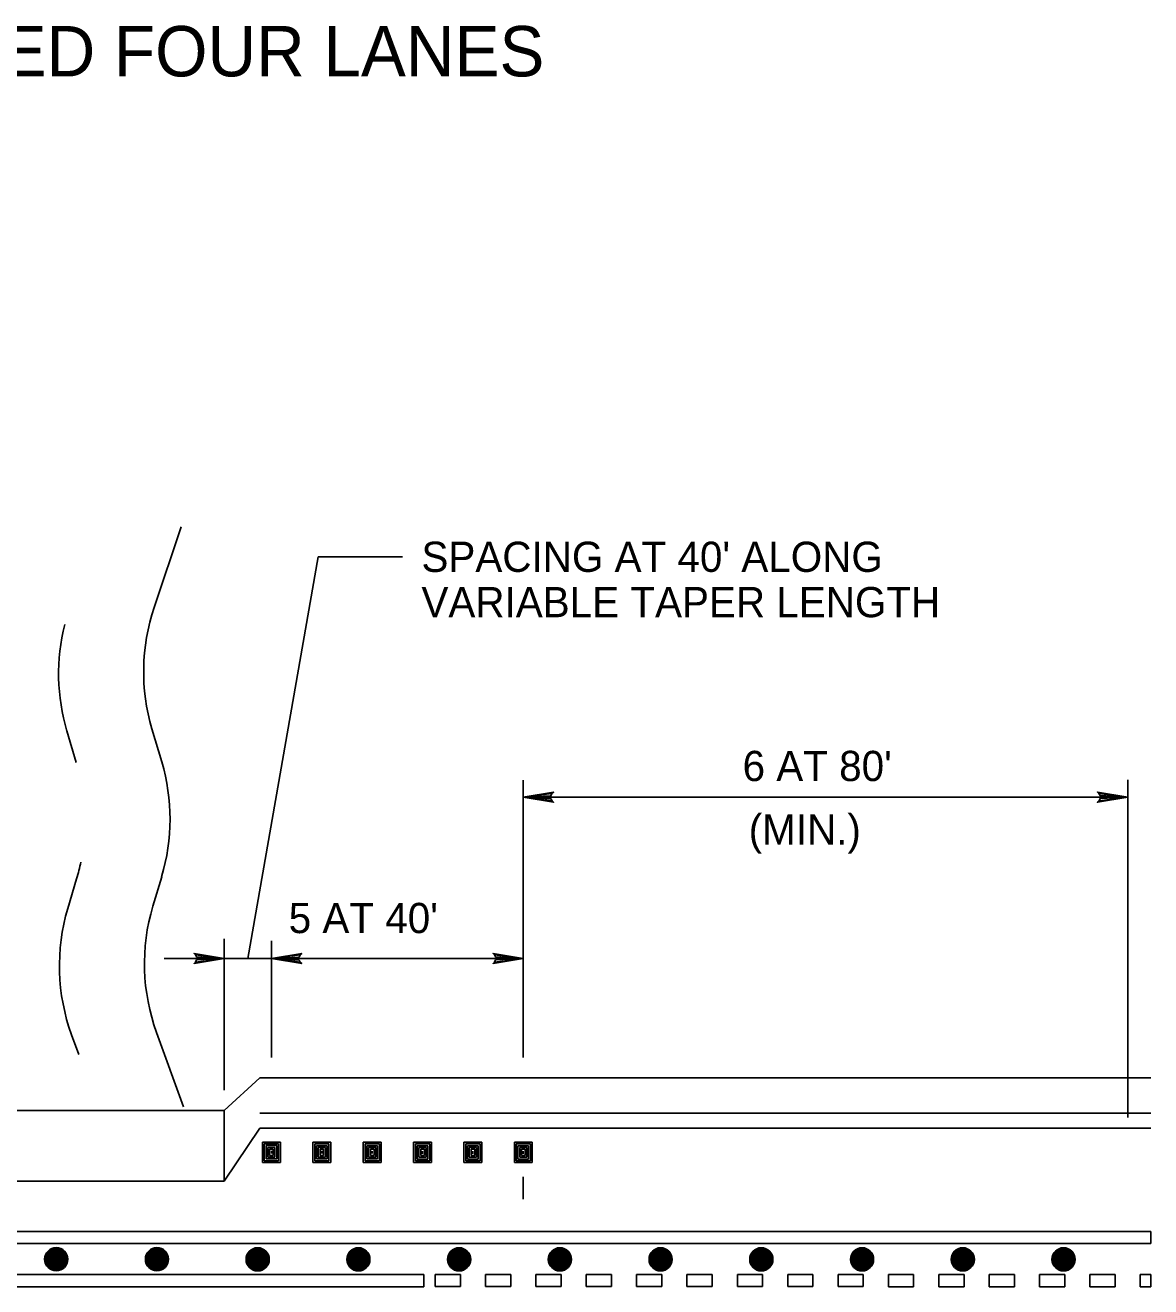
# Model space of a CAD drawing. Extents: x 639362 to 641108, y 298458 to 299646.
# Drawn here: x 640689.2 to 640800.9, y 299355.1 to 299480.3 of the extents above; entities that cross this region are included whole.
import ezdxf

# ---------------------------------------------------------------- set-up
doc = ezdxf.new("R2010")
doc.units = 0
doc.layers.add('2', color=7, linetype='Continuous')
doc.layers.add('3', color=7, linetype='Continuous')

# ---------------------------------------------------------------- blocks, each defined once
blk = doc.blocks.new('RARROW')
at = {"layer": '3'}
blk.add_lwpolyline([(-2.2695, 0.285), (-2.184875, 0.12075), (0, 0), (-2.2695, 0.285), (-2.38575, 0.384625), (0, 0), (-2.183125, -0.108), (-2.262875, -0.2705), (0, 0), (-2.38575, -0.379125), (-2.262875, -0.2705)], dxfattribs=at)

msp = doc.modelspace()

# ---------------------------------------------------------------- linework, layer by layer
at = {"layer": '2'}
for p, q in [((640704.67, 299430.52), (640701.99, 299422.54)), ((640718.27, 299427.55), (640711.31, 299387.69)), ((640718.27, 299427.55), (640726.64, 299427.55)), ((640693.33, 299410.27), (640694.26, 299407.14)), ((640701.77, 299410.48), (640702.75, 299407.2)), ((640738.64, 299405.38), (640738.64, 299377.85)), ((640798.64, 299405.43), (640798.64, 299371.92)), ((640738.64, 299403.7), (640798.64, 299403.7)), ((640702.74, 299395.81), (640701.86, 299392.88)), ((640694.3, 299395.6), (640693.42, 299392.66)), ((640708.95, 299389.65), (640708.95, 299374.61)), ((640713.64, 299389.43), (640713.64, 299377.85)), ((640703, 299387.69), (640713.64, 299387.69)), ((640713.64, 299387.69), (640738.64, 299387.69)), ((640693.79, 299380.12), (640694.51, 299378.15)), ((640702.24, 299380.33), (640704.91, 299372.97)), ((640712.47, 299375.85), (640708.95, 299372.61)), ((640712.47, 299375.85), (640800.93, 299375.85)), ((640671.45, 299372.61), (640708.95, 299372.61)), ((640708.95, 299372.61), (640708.95, 299365.58)), ((640712.47, 299372.35), (640800.93, 299372.35)), ((640712.47, 299370.85), (640708.95, 299365.58)), ((640712.47, 299370.85), (640800.93, 299370.85)), ((640712.75, 299369.47), (640714.53, 299369.47)), ((640712.75, 299367.43), (640712.75, 299369.47)), ((640714.53, 299369.47), (640714.53, 299367.43)), ((640717.75, 299369.47), (640719.53, 299369.47)), ((640717.75, 299367.43), (640717.75, 299369.47)), ((640719.53, 299369.47), (640719.53, 299367.43)), ((640722.75, 299369.47), (640724.53, 299369.47)), ((640722.75, 299367.43), (640722.75, 299369.47)), ((640724.53, 299369.47), (640724.53, 299367.43)), ((640727.75, 299369.47), (640729.53, 299369.47)), ((640727.75, 299367.43), (640727.75, 299369.47)), ((640729.53, 299369.47), (640729.53, 299367.43)), ((640732.75, 299369.47), (640734.53, 299369.47)), ((640732.75, 299367.43), (640732.75, 299369.47)), ((640734.53, 299369.47), (640734.53, 299367.43)), ((640737.75, 299369.47), (640739.53, 299369.47)), ((640737.75, 299367.43), (640737.75, 299369.47)), ((640739.53, 299369.47), (640739.53, 299367.43)), ((640712.93, 299369.29), (640714.35, 299369.29)), ((640712.93, 299367.61), (640712.93, 299369.29)), ((640713.11, 299369.12), (640714.17, 299369.12)), ((640713.11, 299367.79), (640713.11, 299369.12)), ((640713.28, 299367.96), (640713.28, 299368.94)), ((640713.28, 299368.94), (640713.99, 299368.94)), ((640713.46, 299368.76), (640713.82, 299368.76)), ((640713.46, 299368.14), (640713.46, 299368.76)), ((640713.82, 299368.14), (640713.46, 299368.14)), ((640713.64, 299368.59), (640713.64, 299368.32)), ((640713.82, 299368.76), (640713.82, 299368.14)), ((640713.99, 299368.94), (640713.99, 299367.96)), ((640714.17, 299369.12), (640714.17, 299367.79)), ((640714.35, 299369.29), (640714.35, 299367.61)), ((640717.93, 299369.29), (640719.35, 299369.29)), ((640717.93, 299367.61), (640717.93, 299369.29)), ((640718.11, 299369.11), (640719.17, 299369.11)), ((640718.11, 299367.79), (640718.11, 299369.11)), ((640718.28, 299367.96), (640718.28, 299368.94)), ((640718.28, 299368.94), (640718.99, 299368.94)), ((640718.46, 299368.76), (640718.82, 299368.76)), ((640718.46, 299368.14), (640718.46, 299368.76)), ((640718.82, 299368.14), (640718.46, 299368.14)), ((640718.64, 299368.59), (640718.64, 299368.32)), ((640718.82, 299368.76), (640718.82, 299368.14)), ((640718.99, 299368.94), (640718.99, 299367.96)), ((640719.17, 299369.11), (640719.17, 299367.79)), ((640719.35, 299369.29), (640719.35, 299367.61)), ((640722.93, 299369.29), (640724.35, 299369.29)), ((640722.93, 299367.61), (640722.93, 299369.29)), ((640723.11, 299369.11), (640724.17, 299369.11)), ((640723.11, 299367.79), (640723.11, 299369.11)), ((640723.28, 299367.96), (640723.28, 299368.94)), ((640723.28, 299368.94), (640723.99, 299368.94)), ((640723.46, 299368.76), (640723.82, 299368.76)), ((640723.46, 299368.14), (640723.46, 299368.76)), ((640723.82, 299368.14), (640723.46, 299368.14)), ((640723.64, 299368.58), (640723.64, 299368.32)), ((640723.82, 299368.76), (640723.82, 299368.14)), ((640723.99, 299368.94), (640723.99, 299367.96)), ((640724.17, 299369.11), (640724.17, 299367.79)), ((640724.35, 299369.29), (640724.35, 299367.61)), ((640727.93, 299369.29), (640729.35, 299369.29)), ((640727.93, 299367.61), (640727.93, 299369.29)), ((640728.11, 299369.11), (640729.17, 299369.11)), ((640728.11, 299367.78), (640728.11, 299369.11)), ((640728.28, 299367.96), (640728.28, 299368.94)), ((640728.28, 299368.94), (640728.99, 299368.94)), ((640728.46, 299368.76), (640728.82, 299368.76)), ((640728.46, 299368.14), (640728.46, 299368.76)), ((640728.64, 299368.58), (640728.64, 299368.31)), ((640728.82, 299368.76), (640728.82, 299368.14)), ((640728.99, 299368.94), (640728.99, 299367.96)), ((640729.17, 299369.11), (640729.17, 299367.78)), ((640729.35, 299369.29), (640729.35, 299367.61)), ((640732.93, 299369.29), (640734.35, 299369.29)), ((640732.93, 299367.6), (640732.93, 299369.29)), ((640733.11, 299369.11), (640734.17, 299369.11)), ((640733.11, 299367.78), (640733.11, 299369.11)), ((640733.28, 299367.96), (640733.28, 299368.93)), ((640733.28, 299368.93), (640733.99, 299368.93)), ((640733.46, 299368.76), (640733.82, 299368.76)), ((640733.46, 299368.14), (640733.46, 299368.76)), ((640733.64, 299368.58), (640733.64, 299368.31)), ((640733.82, 299368.76), (640733.82, 299368.14)), ((640733.99, 299368.93), (640733.99, 299367.96)), ((640734.17, 299369.11), (640734.17, 299367.78)), ((640734.35, 299369.29), (640734.35, 299367.6)), ((640737.93, 299369.29), (640739.35, 299369.29)), ((640737.93, 299367.6), (640737.93, 299369.29)), ((640738.11, 299369.11), (640739.17, 299369.11)), ((640738.11, 299367.78), (640738.11, 299369.11)), ((640738.28, 299367.96), (640738.28, 299368.93)), ((640738.28, 299368.93), (640738.99, 299368.93)), ((640738.46, 299368.76), (640738.82, 299368.76)), ((640738.46, 299368.14), (640738.46, 299368.76)), ((640738.64, 299368.58), (640738.64, 299368.31)), ((640738.82, 299368.76), (640738.82, 299368.14)), ((640738.99, 299368.93), (640738.99, 299367.96)), ((640739.17, 299369.11), (640739.17, 299367.78)), ((640739.35, 299369.29), (640739.35, 299367.6)), ((640714.53, 299367.43), (640712.75, 299367.43)), ((640714.35, 299367.61), (640712.93, 299367.61)), ((640714.17, 299367.79), (640713.11, 299367.79)), ((640713.99, 299367.96), (640713.28, 299367.96)), ((640719.53, 299367.43), (640717.75, 299367.43)), ((640719.35, 299367.61), (640717.93, 299367.61)), ((640719.17, 299367.79), (640718.11, 299367.79)), ((640718.99, 299367.96), (640718.28, 299367.96)), ((640724.53, 299367.43), (640722.75, 299367.43)), ((640724.35, 299367.61), (640722.93, 299367.61)), ((640724.17, 299367.79), (640723.11, 299367.79)), ((640723.99, 299367.96), (640723.28, 299367.96)), ((640729.53, 299367.43), (640727.75, 299367.43)), ((640729.35, 299367.61), (640727.93, 299367.61)), ((640729.17, 299367.78), (640728.11, 299367.78)), ((640728.99, 299367.96), (640728.28, 299367.96)), ((640728.82, 299368.14), (640728.46, 299368.14)), ((640734.53, 299367.43), (640732.75, 299367.43)), ((640734.35, 299367.6), (640732.93, 299367.6)), ((640734.17, 299367.78), (640733.11, 299367.78)), ((640733.99, 299367.96), (640733.28, 299367.96)), ((640733.82, 299368.14), (640733.46, 299368.14)), ((640739.53, 299367.43), (640737.75, 299367.43)), ((640739.35, 299367.6), (640737.93, 299367.6)), ((640739.17, 299367.78), (640738.11, 299367.78)), ((640738.99, 299367.96), (640738.28, 299367.96)), ((640738.82, 299368.14), (640738.46, 299368.14)), ((640738.64, 299366.01), (640738.64, 299363.8)), ((640671.45, 299365.58), (640708.95, 299365.58)), ((640652.18, 299360.61), (640800.93, 299360.61)), ((640800.93, 299359.41), (640652.18, 299359.41)), ((640800.93, 299360.61), (640800.93, 299359.41)), ((640577.73, 299356.31), (640728.77, 299356.31)), ((640728.77, 299356.31), (640728.77, 299355.11)), ((640729.89, 299356.33), (640729.89, 299355.13)), ((640732.39, 299356.33), (640729.89, 299356.33)), ((640732.39, 299355.13), (640732.39, 299356.33)), ((640734.89, 299356.33), (640734.89, 299355.13)), ((640737.39, 299356.33), (640734.89, 299356.33)), ((640737.39, 299355.13), (640737.39, 299356.33)), ((640739.89, 299356.32), (640739.89, 299355.12)), ((640742.39, 299356.32), (640739.89, 299356.32)), ((640742.39, 299355.12), (640742.39, 299356.32)), ((640744.89, 299356.32), (640744.89, 299355.12)), ((640747.39, 299356.32), (640744.89, 299356.32)), ((640747.39, 299355.12), (640747.39, 299356.32)), ((640749.89, 299356.32), (640749.89, 299355.12)), ((640752.39, 299356.32), (640749.89, 299356.32)), ((640752.39, 299355.12), (640752.39, 299356.32)), ((640754.89, 299356.32), (640754.89, 299355.12)), ((640757.39, 299356.32), (640754.89, 299356.32)), ((640757.39, 299355.12), (640757.39, 299356.32)), ((640759.89, 299356.32), (640759.89, 299355.12)), ((640762.39, 299356.32), (640759.89, 299356.32)), ((640762.39, 299355.12), (640762.39, 299356.32)), ((640764.89, 299356.32), (640764.89, 299355.12)), ((640767.39, 299356.32), (640764.89, 299356.32)), ((640767.39, 299355.12), (640767.39, 299356.32)), ((640769.89, 299356.32), (640769.89, 299355.12)), ((640772.39, 299356.32), (640769.89, 299356.32)), ((640772.39, 299355.12), (640772.39, 299356.32)), ((640774.89, 299356.32), (640774.89, 299355.11)), ((640777.39, 299356.32), (640774.89, 299356.32)), ((640777.39, 299355.11), (640777.39, 299356.32)), ((640779.89, 299356.31), (640779.89, 299355.11)), ((640782.39, 299356.31), (640779.89, 299356.31)), ((640782.39, 299355.11), (640782.39, 299356.31)), ((640784.89, 299356.31), (640784.89, 299355.11)), ((640787.39, 299356.31), (640784.89, 299356.31)), ((640787.39, 299355.11), (640787.39, 299356.31)), ((640789.89, 299356.31), (640789.89, 299355.11)), ((640792.39, 299356.31), (640789.89, 299356.31)), ((640792.39, 299355.11), (640792.39, 299356.31)), ((640794.89, 299356.31), (640794.89, 299355.11)), ((640797.39, 299356.31), (640794.89, 299356.31)), ((640797.39, 299355.11), (640797.39, 299356.31)), ((640799.89, 299355.11), (640799.89, 299356.31)), ((640799.89, 299356.31), (640800.93, 299356.31)), ((640800.93, 299356.31), (640800.93, 299355.11)), ((640728.77, 299355.11), (640577.73, 299355.11)), ((640729.89, 299355.13), (640732.39, 299355.13)), ((640734.89, 299355.12), (640737.39, 299355.12)), ((640739.89, 299355.12), (640742.39, 299355.12)), ((640744.89, 299355.12), (640747.39, 299355.12)), ((640749.89, 299355.12), (640752.39, 299355.12)), ((640754.89, 299355.12), (640757.39, 299355.12)), ((640759.89, 299355.12), (640762.39, 299355.12)), ((640764.89, 299355.12), (640767.39, 299355.12)), ((640769.89, 299355.12), (640772.39, 299355.12)), ((640774.89, 299355.11), (640777.39, 299355.11)), ((640779.89, 299355.11), (640782.39, 299355.11)), ((640784.89, 299355.11), (640787.39, 299355.11)), ((640789.89, 299355.11), (640792.39, 299355.11)), ((640794.89, 299355.11), (640797.39, 299355.11)), ((640800.93, 299355.11), (640799.89, 299355.11)), ((640799.89, 299355.11), (640799.89, 299355.11))]:
    msp.add_line(p, q, dxfattribs=at)
for centre, radius in [((640692.27, 299357.84), 1.15), ((640692.27, 299357.84), 1.07), ((640692.27, 299357.84), 0.985), ((640692.27, 299357.84), 0.904), ((640692.27, 299357.84), 0.822), ((640692.27, 299357.84), 0.741), ((640692.27, 299357.84), 0.659), ((640692.27, 299357.84), 0.578), ((640692.27, 299357.84), 0.496), ((640692.27, 299357.84), 0.414), ((640692.27, 299357.84), 0.333), ((640702.27, 299357.84), 1.15), ((640702.27, 299357.84), 1.07), ((640702.27, 299357.84), 0.985), ((640702.27, 299357.84), 0.904), ((640702.27, 299357.84), 0.822), ((640702.27, 299357.84), 0.741), ((640702.27, 299357.84), 0.659), ((640702.27, 299357.84), 0.578), ((640702.27, 299357.84), 0.496), ((640702.27, 299357.84), 0.414), ((640702.27, 299357.84), 0.333), ((640712.27, 299357.83), 1.15), ((640712.27, 299357.83), 1.07), ((640712.27, 299357.83), 0.985), ((640712.27, 299357.83), 0.904), ((640712.27, 299357.83), 0.822), ((640712.27, 299357.83), 0.741), ((640712.27, 299357.83), 0.659), ((640712.27, 299357.83), 0.578), ((640712.27, 299357.83), 0.496), ((640712.27, 299357.83), 0.414), ((640712.27, 299357.83), 0.333), ((640722.27, 299357.83), 1.15), ((640722.27, 299357.83), 1.07), ((640722.27, 299357.83), 0.985), ((640722.27, 299357.83), 0.904), ((640722.27, 299357.83), 0.822), ((640722.27, 299357.83), 0.741), ((640722.27, 299357.83), 0.659), ((640722.27, 299357.83), 0.578), ((640722.27, 299357.83), 0.496), ((640722.27, 299357.83), 0.414), ((640722.27, 299357.83), 0.333), ((640732.27, 299357.83), 1.15), ((640732.27, 299357.83), 1.07), ((640732.27, 299357.83), 0.985), ((640732.27, 299357.83), 0.904), ((640732.27, 299357.83), 0.822), ((640732.27, 299357.83), 0.741), ((640732.27, 299357.83), 0.659), ((640732.27, 299357.83), 0.578), ((640732.27, 299357.83), 0.496), ((640732.27, 299357.83), 0.414), ((640732.27, 299357.83), 0.333), ((640742.27, 299357.83), 1.15), ((640742.27, 299357.83), 1.07), ((640742.27, 299357.83), 0.985), ((640742.27, 299357.83), 0.904), ((640742.27, 299357.83), 0.822), ((640742.27, 299357.83), 0.741), ((640742.27, 299357.83), 0.659), ((640742.27, 299357.83), 0.578), ((640742.27, 299357.83), 0.496), ((640742.27, 299357.83), 0.414), ((640742.27, 299357.83), 0.333), ((640752.27, 299357.83), 1.15), ((640752.27, 299357.83), 1.07), ((640752.27, 299357.83), 0.985), ((640752.27, 299357.83), 0.904), ((640752.27, 299357.83), 0.822), ((640752.27, 299357.83), 0.741), ((640752.27, 299357.83), 0.659), ((640752.27, 299357.83), 0.578), ((640752.27, 299357.83), 0.496), ((640752.27, 299357.83), 0.414), ((640752.27, 299357.83), 0.333), ((640762.27, 299357.83), 1.15), ((640762.27, 299357.83), 1.07), ((640762.27, 299357.83), 0.985), ((640762.27, 299357.83), 0.904), ((640762.27, 299357.83), 0.822), ((640762.27, 299357.83), 0.741), ((640762.27, 299357.83), 0.659), ((640762.27, 299357.83), 0.578), ((640762.27, 299357.83), 0.496), ((640762.27, 299357.83), 0.414), ((640762.27, 299357.83), 0.333), ((640772.27, 299357.83), 1.15), ((640772.27, 299357.83), 1.07), ((640772.27, 299357.83), 0.985), ((640772.27, 299357.83), 0.904), ((640772.27, 299357.83), 0.822), ((640772.27, 299357.83), 0.741), ((640772.27, 299357.83), 0.659), ((640772.27, 299357.83), 0.578), ((640772.27, 299357.83), 0.496), ((640772.27, 299357.83), 0.414), ((640772.27, 299357.83), 0.333), ((640782.27, 299357.83), 1.15), ((640782.27, 299357.83), 1.07), ((640782.27, 299357.83), 0.985), ((640782.27, 299357.83), 0.904), ((640782.27, 299357.83), 0.822), ((640782.27, 299357.83), 0.741), ((640782.27, 299357.83), 0.659), ((640782.27, 299357.83), 0.578), ((640782.27, 299357.83), 0.496), ((640782.27, 299357.83), 0.414), ((640782.27, 299357.83), 0.333), ((640792.27, 299357.83), 1.15), ((640792.27, 299357.83), 1.07), ((640792.27, 299357.83), 0.985), ((640792.27, 299357.83), 0.904), ((640792.27, 299357.83), 0.822), ((640792.27, 299357.83), 0.741), ((640792.27, 299357.83), 0.659), ((640792.27, 299357.83), 0.578), ((640792.27, 299357.83), 0.496), ((640792.27, 299357.83), 0.414), ((640792.27, 299357.83), 0.333), ((640692.27, 299357.84), 0.251), ((640692.27, 299357.84), 0.17), ((640692.27, 299357.84), 0.0881), ((640702.27, 299357.84), 0.251), ((640702.27, 299357.84), 0.17), ((640702.27, 299357.84), 0.0881), ((640712.27, 299357.83), 0.251), ((640712.27, 299357.83), 0.17), ((640712.27, 299357.83), 0.0881), ((640722.27, 299357.83), 0.251), ((640722.27, 299357.83), 0.17), ((640722.27, 299357.83), 0.0881), ((640732.27, 299357.83), 0.251), ((640732.27, 299357.83), 0.17), ((640732.27, 299357.83), 0.0881), ((640742.27, 299357.83), 0.251), ((640742.27, 299357.83), 0.17), ((640742.27, 299357.83), 0.0881), ((640752.27, 299357.83), 0.251), ((640752.27, 299357.83), 0.17), ((640752.27, 299357.83), 0.0881), ((640762.27, 299357.83), 0.251), ((640762.27, 299357.83), 0.17), ((640762.27, 299357.83), 0.0881), ((640772.27, 299357.83), 0.251), ((640772.27, 299357.83), 0.17), ((640772.27, 299357.83), 0.0881), ((640782.27, 299357.83), 0.251), ((640782.27, 299357.83), 0.17), ((640782.27, 299357.83), 0.0881), ((640792.27, 299357.83), 0.251), ((640792.27, 299357.83), 0.17), ((640792.27, 299357.83), 0.0881)]:
    msp.add_circle(centre, radius, dxfattribs=at)
for centre, start, end in [((640720.95, 299416.16), 161.4259, 196.5084), ((640712.51, 299415.95), 165.8785, 196.5084), ((640683.57, 299401.52), 343.4142, 16.5084), ((640675.13, 299401.31), 343.4142, 348.3347), ((640712.59, 299386.95), 163.4142, 199.9879), ((640721.03, 299387.17), 163.4142, 199.9879)]:
    msp.add_arc(centre, 20, start, end, dxfattribs=at)

# ---------------------------------------------------------------- block references
at = {"layer": '2', "xscale": 1.2574347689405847, "yscale": 1.3092961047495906, "rotation": 180}
for p in [(640738.64, 299403.7), (640713.64, 299387.69)]:
    msp.add_blockref('RARROW', p, dxfattribs=at)
at = {"layer": '2', "xscale": 1.2574347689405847, "yscale": 1.3092961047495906}
for p in [(640798.64, 299403.7), (640708.95, 299387.69), (640738.64, 299387.69)]:
    msp.add_blockref('RARROW', p, dxfattribs=at)

# ---------------------------------------------------------------- texts
at = {"layer": '2'}
for s, height, p in [('UNDIVIDED FOUR LANES', 5, (640659.37, 299475.24)), ("SPACING AT 40' ALONG", 3, (640728.53, 299426.06)), ('VARIABLE TAPER LENGTH', 3, (640728.53, 299421.56)), ("6 AT 80'", 3, (640760.41, 299405.3)), (' (MIN.)', 3, (640759.9, 299398.99)), ("5 AT 40'", 3, (640715.35, 299390.21))]:
    msp.add_text(s, height=height, dxfattribs=at).set_placement(p)

doc.saveas('drawing.dxf')
